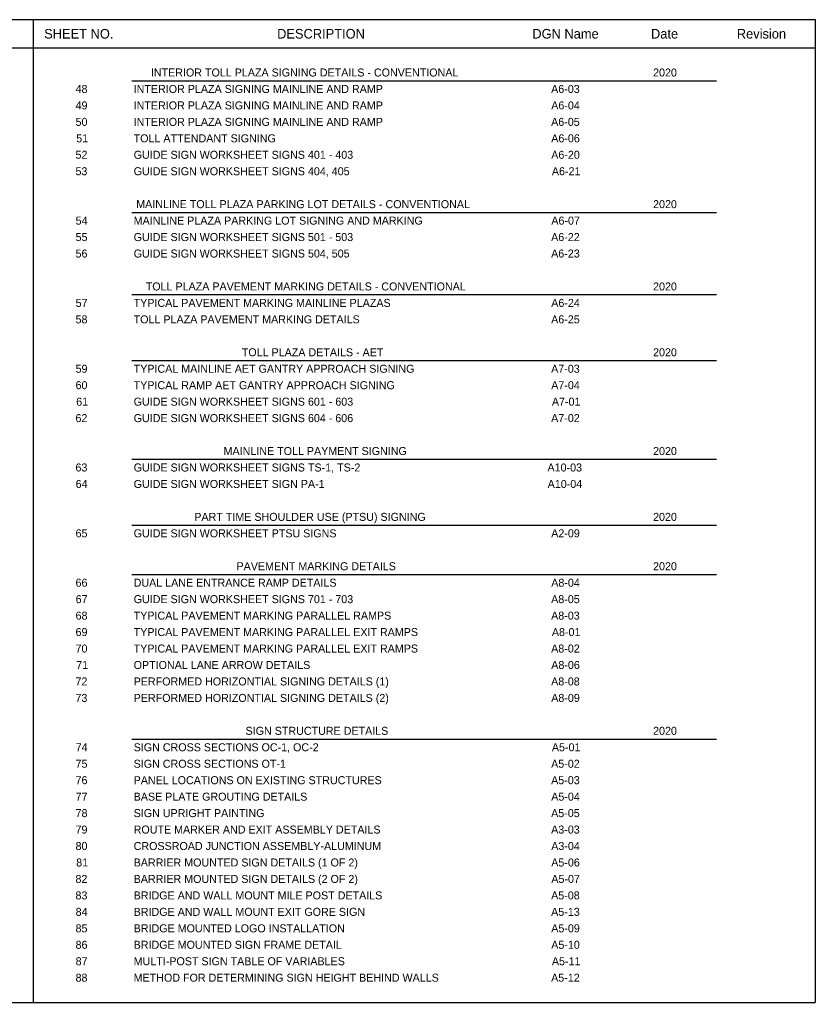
# Model space of a CAD drawing. Extents: x 2479979.8 to 2480018.9, y 3680687.9 to 3680700.6.
# Drawn here: x 2480010.15 to 2480018.85, y 3680689.81 to 3680700.55 of the extents above; entities that cross this region are included whole.
import ezdxf

# ---------------------------------------------------------------- set-up
doc = ezdxf.new("R2010")
doc.units = 0
doc.layers.add('SumBoxLines_dp', color=7, linetype='Continuous')
doc.layers.add('TextLabel', color=7, linetype='Continuous')

msp = doc.modelspace()

# ---------------------------------------------------------------- linework, layer by layer
at = {"layer": 'SumBoxLines_dp'}
for p, q in [((2480001.458, 3680700.555), (2480018.85, 3680700.555)), ((2480010.3, 3680700.555), (2480010.3, 3680689.807)), ((2480010.3, 3680700.555), (2480010.3, 3680689.807)), ((2480018.85, 3680700.555), (2480018.85, 3680689.807)), ((2480001.458, 3680700.247), (2480018.85, 3680700.247)), ((2480001.458, 3680700.247), (2480018.85, 3680700.247)), ((2480011.38, 3680699.887), (2480017.77, 3680699.887)), ((2480011.38, 3680699.887), (2480017.77, 3680699.887)), ((2480011.38, 3680698.447), (2480017.77, 3680698.447)), ((2480011.38, 3680698.447), (2480017.77, 3680698.447)), ((2480011.38, 3680697.547), (2480017.77, 3680697.547)), ((2480011.38, 3680697.547), (2480017.77, 3680697.547)), ((2480011.38, 3680696.827), (2480017.77, 3680696.827)), ((2480011.38, 3680696.827), (2480017.77, 3680696.827)), ((2480011.38, 3680695.747), (2480017.77, 3680695.747)), ((2480011.38, 3680695.747), (2480017.77, 3680695.747)), ((2480011.38, 3680695.027), (2480017.77, 3680695.027)), ((2480011.38, 3680695.027), (2480017.77, 3680695.027)), ((2480011.38, 3680694.487), (2480017.77, 3680694.487)), ((2480011.38, 3680694.487), (2480017.77, 3680694.487)), ((2480011.38, 3680692.687), (2480017.77, 3680692.687)), ((2480011.38, 3680692.687), (2480017.77, 3680692.687)), ((2480001.458, 3680689.807), (2480018.85, 3680689.807)), ((2480001.458, 3680689.807), (2480018.85, 3680689.807))]:
    msp.add_line(p, q, dxfattribs=at)

# ---------------------------------------------------------------- texts
at = {"layer": 'TextLabel'}
for s, height, p in [('SHEET NO.', 0.105, (2480010.422, 3680700.348)), ('DESCRIPTION', 0.105, (2480012.968, 3680700.348)), ('DGN Name', 0.105, (2480015.757, 3680700.348)), ('Date', 0.105, (2480017.054, 3680700.348)), ('Revision', 0.105, (2480017.992, 3680700.348)), ('INTERIOR TOLL PLAZA SIGNING DETAILS - CONVENTIONAL', 0.0875, (2480011.588, 3680699.933)), ('2020', 0.0875, (2480017.077, 3680699.933)), ('48', 0.0875, (2480010.765, 3680699.753)), ('INTERIOR PLAZA SIGNING MAINLINE AND RAMP', 0.0875, (2480011.4, 3680699.753)), ('A6-03', 0.0875, (2480015.963, 3680699.753)), ('49', 0.0875, (2480010.765, 3680699.573)), ('INTERIOR PLAZA SIGNING MAINLINE AND RAMP', 0.0875, (2480011.4, 3680699.573)), ('A6-04', 0.0875, (2480015.964, 3680699.573)), ('50', 0.0875, (2480010.765, 3680699.393)), ('INTERIOR PLAZA SIGNING MAINLINE AND RAMP', 0.0875, (2480011.4, 3680699.393)), ('A6-05', 0.0875, (2480015.963, 3680699.393)), ('51', 0.0875, (2480010.772, 3680699.213)), ('TOLL ATTENDANT SIGNING', 0.0875, (2480011.4, 3680699.213)), ('A6-06', 0.0875, (2480015.964, 3680699.213)), ('52', 0.0875, (2480010.764, 3680699.033)), ('GUIDE SIGN WORKSHEET SIGNS 401 - 403', 0.0875, (2480011.4, 3680699.033)), ('A6-20', 0.0875, (2480015.964, 3680699.033)), ('53', 0.0875, (2480010.764, 3680698.853)), ('GUIDE SIGN WORKSHEET SIGNS 404, 405', 0.0875, (2480011.4, 3680698.853)), ('A6-21', 0.0875, (2480015.971, 3680698.853)), ('MAINLINE TOLL PLAZA PARKING LOT DETAILS - CONVENTIONAL', 0.0875, (2480011.428, 3680698.493)), ('2020', 0.0875, (2480017.077, 3680698.493)), ('54', 0.0875, (2480010.766, 3680698.313)), ('MAINLINE PLAZA PARKING LOT SIGNING AND MARKING', 0.0875, (2480011.4, 3680698.313)), ('A6-07', 0.0875, (2480015.965, 3680698.313)), ('55', 0.0875, (2480010.765, 3680698.133)), ('GUIDE SIGN WORKSHEET SIGNS 501 - 503', 0.0875, (2480011.4, 3680698.133)), ('A6-22', 0.0875, (2480015.963, 3680698.133)), ('56', 0.0875, (2480010.765, 3680697.953)), ('GUIDE SIGN WORKSHEET SIGNS 504, 505', 0.0875, (2480011.4, 3680697.953)), ('A6-23', 0.0875, (2480015.963, 3680697.953)), ('TOLL PLAZA PAVEMENT MARKING DETAILS - CONVENTIONAL', 0.0875, (2480011.532, 3680697.593)), ('2020', 0.0875, (2480017.077, 3680697.593)), ('57', 0.0875, (2480010.766, 3680697.413)), ('TYPICAL PAVEMENT MARKING MAINLINE PLAZAS', 0.0875, (2480011.4, 3680697.413)), ('A6-24', 0.0875, (2480015.964, 3680697.413)), ('58', 0.0875, (2480010.765, 3680697.233)), ('TOLL PLAZA PAVEMENT MARKING DETAILS', 0.0875, (2480011.4, 3680697.233)), ('A6-25', 0.0875, (2480015.963, 3680697.233)), ('TOLL PLAZA DETAILS - AET', 0.0875, (2480012.582, 3680696.873)), ('2020', 0.0875, (2480017.077, 3680696.873)), ('59', 0.0875, (2480010.765, 3680696.693)), ('TYPICAL MAINLINE AET GANTRY APPROACH SIGNING', 0.0875, (2480011.4, 3680696.693)), ('A7-03', 0.0875, (2480015.963, 3680696.693)), ('60', 0.0875, (2480010.765, 3680696.513)), ('TYPICAL RAMP AET GANTRY APPROACH SIGNING', 0.0875, (2480011.4, 3680696.513)), ('A7-04', 0.0875, (2480015.964, 3680696.513)), ('61', 0.0875, (2480010.772, 3680696.333)), ('GUIDE SIGN WORKSHEET SIGNS 601 - 603', 0.0875, (2480011.4, 3680696.333)), ('A7-01', 0.0875, (2480015.971, 3680696.333)), ('62', 0.0875, (2480010.764, 3680696.153)), ('GUIDE SIGN WORKSHEET SIGNS 604 - 606', 0.0875, (2480011.4, 3680696.153)), ('A7-02', 0.0875, (2480015.963, 3680696.153)), ('MAINLINE TOLL PAYMENT SIGNING', 0.0875, (2480012.383, 3680695.793)), ('2020', 0.0875, (2480017.077, 3680695.793)), ('63', 0.0875, (2480010.764, 3680695.613)), ('GUIDE SIGN WORKSHEET SIGNS TS-1, TS-2', 0.0875, (2480011.4, 3680695.613)), ('A10-03', 0.0875, (2480015.923, 3680695.613)), ('64', 0.0875, (2480010.766, 3680695.433)), ('GUIDE SIGN WORKSHEET SIGN PA-1', 0.0875, (2480011.4, 3680695.433)), ('A10-04', 0.0875, (2480015.925, 3680695.433)), ('PART TIME SHOULDER USE (PTSU) SIGNING', 0.0875, (2480012.063, 3680695.073)), ('2020', 0.0875, (2480017.077, 3680695.073)), ('65', 0.0875, (2480010.765, 3680694.893)), ('GUIDE SIGN WORKSHEET PTSU SIGNS', 0.0875, (2480011.4, 3680694.893)), ('A2-09', 0.0875, (2480015.964, 3680694.893)), ('PAVEMENT MARKING DETAILS', 0.0875, (2480012.524, 3680694.533)), ('2020', 0.0875, (2480017.077, 3680694.533)), ('66', 0.0875, (2480010.765, 3680694.353)), ('DUAL LANE ENTRANCE RAMP DETAILS', 0.0875, (2480011.4, 3680694.353)), ('A8-04', 0.0875, (2480015.964, 3680694.353)), ('67', 0.0875, (2480010.766, 3680694.173)), ('GUIDE SIGN WORKSHEET SIGNS 701 - 703', 0.0875, (2480011.4, 3680694.173)), ('A8-05', 0.0875, (2480015.963, 3680694.173)), ('68', 0.0875, (2480010.765, 3680693.993)), ('TYPICAL PAVEMENT MARKING PARALLEL RAMPS', 0.0875, (2480011.4, 3680693.993)), ('A8-03', 0.0875, (2480015.963, 3680693.993)), ('69', 0.0875, (2480010.765, 3680693.813)), ('TYPICAL PAVEMENT MARKING PARALLEL EXIT RAMPS', 0.0875, (2480011.4, 3680693.813)), ('A8-01', 0.0875, (2480015.971, 3680693.813)), ('70', 0.0875, (2480010.765, 3680693.633)), ('TYPICAL PAVEMENT MARKING PARALLEL EXIT RAMPS', 0.0875, (2480011.4, 3680693.633)), ('A8-02', 0.0875, (2480015.963, 3680693.633)), ('71', 0.0875, (2480010.772, 3680693.453)), ('OPTIONAL LANE ARROW DETAILS', 0.0875, (2480011.4, 3680693.453)), ('A8-06', 0.0875, (2480015.964, 3680693.453)), ('72', 0.0875, (2480010.764, 3680693.273)), ('PERFORMED HORIZONTIAL SIGNING DETAILS (1)', 0.0875, (2480011.4, 3680693.273)), ('A8-08', 0.0875, (2480015.963, 3680693.273)), ('73', 0.0875, (2480010.764, 3680693.093)), ('PERFORMED HORIZONTIAL SIGNING DETAILS (2)', 0.0875, (2480011.4, 3680693.093)), ('A8-09', 0.0875, (2480015.964, 3680693.093)), ('SIGN STRUCTURE DETAILS', 0.0875, (2480012.623, 3680692.733)), ('2020', 0.0875, (2480017.077, 3680692.733)), ('74', 0.0875, (2480010.766, 3680692.553)), ('SIGN CROSS SECTIONS OC-1, OC-2', 0.0875, (2480011.4, 3680692.553)), ('A5-01', 0.0875, (2480015.971, 3680692.553)), ('75', 0.0875, (2480010.765, 3680692.373)), ('SIGN CROSS SECTIONS OT-1', 0.0875, (2480011.4, 3680692.373)), ('A5-02', 0.0875, (2480015.963, 3680692.373)), ('76', 0.0875, (2480010.765, 3680692.193)), ('PANEL LOCATIONS ON EXISTING STRUCTURES', 0.0875, (2480011.4, 3680692.193)), ('A5-03', 0.0875, (2480015.963, 3680692.193)), ('77', 0.0875, (2480010.766, 3680692.013)), ('BASE PLATE GROUTING DETAILS', 0.0875, (2480011.4, 3680692.013)), ('A5-04', 0.0875, (2480015.964, 3680692.013)), ('78', 0.0875, (2480010.765, 3680691.833)), ('SIGN UPRIGHT PAINTING', 0.0875, (2480011.4, 3680691.833)), ('A5-05', 0.0875, (2480015.963, 3680691.833)), ('79', 0.0875, (2480010.765, 3680691.653)), ('ROUTE MARKER AND EXIT ASSEMBLY DETAILS', 0.0875, (2480011.4, 3680691.653)), ('A3-03', 0.0875, (2480015.963, 3680691.653)), ('80', 0.0875, (2480010.765, 3680691.473)), ('CROSSROAD JUNCTION ASSEMBLY-ALUMINUM', 0.0875, (2480011.4, 3680691.473)), ('A3-04', 0.0875, (2480015.964, 3680691.473)), ('81', 0.0875, (2480010.772, 3680691.293)), ('BARRIER MOUNTED SIGN DETAILS (1 OF 2)', 0.0875, (2480011.4, 3680691.293)), ('A5-06', 0.0875, (2480015.964, 3680691.293)), ('82', 0.0875, (2480010.764, 3680691.113)), ('BARRIER MOUNTED SIGN DETAILS (2 OF 2)', 0.0875, (2480011.4, 3680691.113)), ('A5-07', 0.0875, (2480015.965, 3680691.113)), ('83', 0.0875, (2480010.764, 3680690.933)), ('BRIDGE AND WALL MOUNT MILE POST DETAILS', 0.0875, (2480011.4, 3680690.933)), ('A5-08', 0.0875, (2480015.963, 3680690.933)), ('84', 0.0875, (2480010.766, 3680690.753)), ('BRIDGE AND WALL MOUNT EXIT GORE SIGN', 0.0875, (2480011.4, 3680690.753)), ('A5-13', 0.0875, (2480015.963, 3680690.753)), ('85', 0.0875, (2480010.765, 3680690.573)), ('BRIDGE MOUNTED LOGO INSTALLATION', 0.0875, (2480011.4, 3680690.573)), ('A5-09', 0.0875, (2480015.964, 3680690.573)), ('86', 0.0875, (2480010.765, 3680690.393)), ('BRIDGE MOUNTED SIGN FRAME DETAIL', 0.0875, (2480011.4, 3680690.393)), ('A5-10', 0.0875, (2480015.964, 3680690.393)), ('87', 0.0875, (2480010.766, 3680690.213)), ('MULTI-POST SIGN TABLE OF VARIABLES', 0.0875, (2480011.4, 3680690.213)), ('A5-11', 0.0875, (2480015.971, 3680690.213)), ('88', 0.0875, (2480010.765, 3680690.033)), ('METHOD FOR DETERMINING SIGN HEIGHT BEHIND WALLS', 0.0875, (2480011.4, 3680690.033)), ('A5-12', 0.0875, (2480015.963, 3680690.033))]:
    msp.add_text(s, height=height, dxfattribs=at).set_placement(p)

doc.saveas('drawing.dxf')
